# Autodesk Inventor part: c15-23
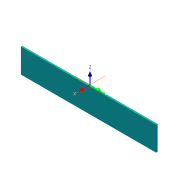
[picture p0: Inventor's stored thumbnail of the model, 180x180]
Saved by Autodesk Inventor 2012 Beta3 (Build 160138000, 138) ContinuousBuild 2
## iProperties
Created: 2011-02
Part Number: c15-23
Material: Default
Document SubType Name: Modeling
Designer: Beta-8540w
Density: 1 g/cm^3
Author: Beta-8540w
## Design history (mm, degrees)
sketch "Sketch1"
  geometry: L1 (-44.45, 7.937)-(44.45, 7.937); L2 (44.45, 7.937)-(44.45, -7.938); L3 (44.45, -7.938)-(-44.45, -7.938); L4 (-44.45, -7.938)-(-44.45, 7.937); 3 further points
  constraints: 8 end point, 2 midpoint, 2 parallel, 1 horizontal, 1 horizontal alignment, 1 perpendicular, 1 vertical alignment
  dimensions: "length" = 88.9 distance of L1.start L1.end; "d1" = 15.875 distance of L3.end L1.start
extrude "Extrusion1" new body sketch "Sketch1" taper "d3" = 0 deg; distance "thickness" = 1
body "Solid1"
other parameters: "d4" = 0, "d5" = 0, "d6" = 0, "d7" = 0, "d8" = 0, "d9" = 0
